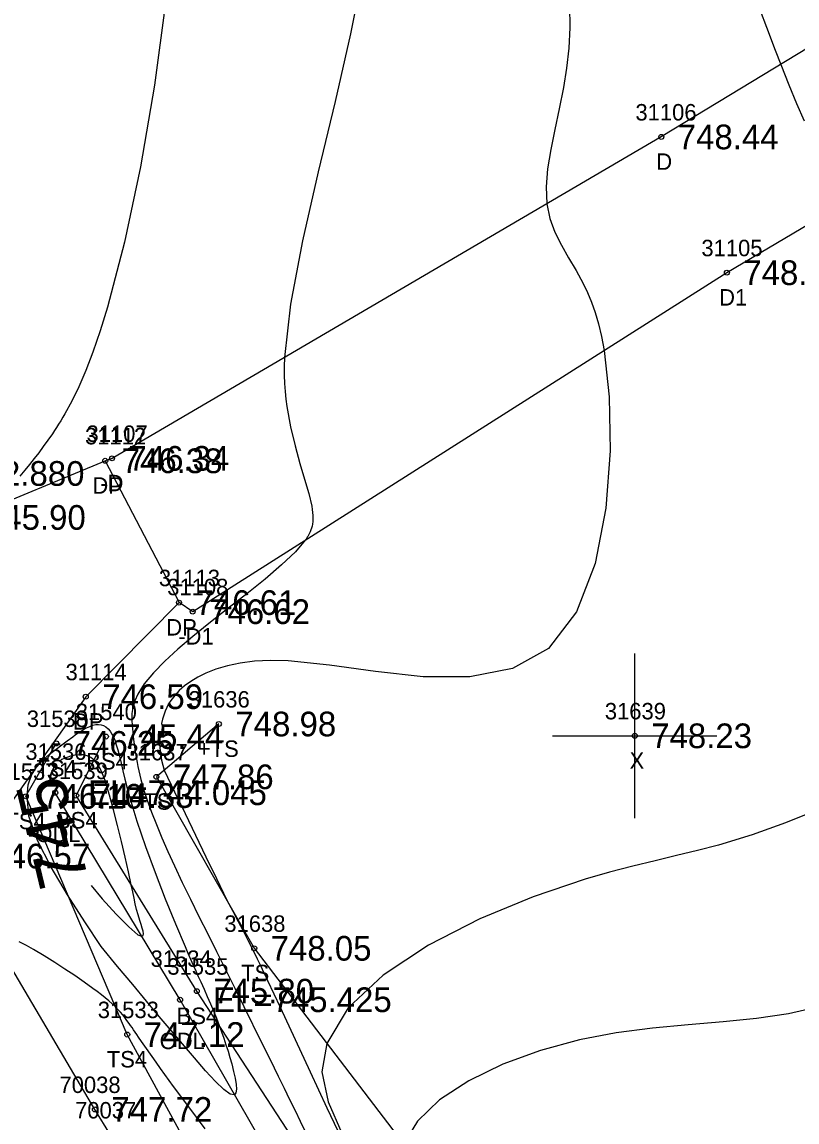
# Model space of a CAD drawing. Extents: x 1376587 to 1378239, y 1000335 to 1003031.
# Drawn here: x 1377894.3 to 1377941.4, y 1000801.1 to 1000868 of the extents above; entities that cross this region are included whole.
import ezdxf

# ---------------------------------------------------------------- set-up
doc = ezdxf.new("R2010")
doc.units = 0
for name, color, linetype in [('RD_DTM_BkLn2', 7, 'Continuous'), ('RD_DTM_BkLn_txCode', 7, 'Continuous'), ('RD_DTM_Major1', 7, 'Continuous'), ('RD_DTM_Major1_Lbl', 7, 'Continuous'), ('RD_DTM_Minor1', 7, 'Continuous'), ('RD_EX_Driveway', 7, 'Continuous'), ('RD_EX_Driveway_txCode', 7, 'Continuous'), ('RD_EX_H2O', 7, 'Continuous'), ('RD_EX_H2O_txCode', 7, 'Continuous'), ('RD_EX_Misc', 7, 'Continuous'), ('RD_EX_Misc_txCode', 7, 'Continuous'), ('RD_EX_Road', 7, 'Continuous'), ('RD_EX_Road_txCode', 7, 'Continuous'), ('RD_EX_TX_Driveway_ELEV', 7, 'Continuous'), ('RD_EX_TX_H2O_ELEV', 7, 'Continuous'), ('RD_EX_TX_Misc_ELEV', 7, 'Continuous'), ('RD_EX_TX_Road_ELEV', 7, 'Continuous'), ('RD_HC_Survey_ELEV', 7, 'Continuous'), ('RD_SMD_Locator', 7, 'Continuous')]:
    doc.layers.add(name, color=color, linetype=linetype)

msp = doc.modelspace()

# ---------------------------------------------------------------- linework, layer by layer
at = {"layer": 'RD_DTM_BkLn2'}
for points in [[(1377906.26, 1000825.275), (1377902.456, 1000822.063), (1377908.408, 1000811.64), (1377936.588, 1000774.744), (1377960.665, 1000733.287), (1377984.073, 1000697.247), (1378009.482, 1000659.726)], [(1378037.054, 1000660.69), (1378019.371, 1000647.154), (1378012.958, 1000645.379), (1378008.902, 1000647.858), (1378005.689, 1000648.466), (1377979.425, 1000689.869), (1377951.959, 1000733.065), (1377926.815, 1000775.481), (1377904.915, 1000809.034), (1377897.581, 1000820.924), (1377899.385, 1000824.511)], [(1378008.67, 1000646.807), (1378003.766, 1000643.675), (1378001.404, 1000645.1), (1377976.657, 1000689.064), (1377948.341, 1000730.353), (1377932.085, 1000752.211), (1377921.755, 1000767.644), (1377900.683, 1000806.395), (1377894.514, 1000820.878), (1377896.367, 1000824.095)]]:
    msp.add_lwpolyline(points, dxfattribs=at)
at = {"layer": 'RD_DTM_Major1'}
for points in [[(1377901.558, 1000812.387), (1377901.642, 1000812.416), (1377901.668, 1000812.517), (1377901.647, 1000812.675), (1377901.595, 1000812.873), (1377901.524, 1000813.095), (1377901.448, 1000813.324), (1377901.343, 1000813.667), (1377901.254, 1000814.002), (1377901.173, 1000814.341), (1377901.097, 1000814.695), (1377901.018, 1000815.075), (1377900.931, 1000815.493), (1377900.76, 1000816.287), (1377900.56, 1000817.18), (1377900.338, 1000818.131), (1377900.1, 1000819.103), (1377899.855, 1000820.057), (1377899.609, 1000820.954), (1377899.471, 1000821.42), (1377899.332, 1000821.85), (1377899.186, 1000822.237), (1377899.03, 1000822.576), (1377898.858, 1000822.86), (1377898.668, 1000823.085), (1377898.461, 1000823.241), (1377898.237, 1000823.342), (1377897.998, 1000823.393), (1377897.749, 1000823.401), (1377897.495, 1000823.372), (1377897.238, 1000823.314), (1377897.059, 1000823.259), (1377896.883, 1000823.192), (1377896.71, 1000823.114), (1377896.652, 1000823.084)], [(1377898.483, 1000815.461), (1377899.162, 1000814.653), (1377900.012, 1000813.716), (1377900.772, 1000812.944), (1377901.326, 1000812.46), (1377901.558, 1000812.387)], [(1377942.592, 1000808.041), (1377940.914, 1000807.665), (1377938.966, 1000807.372), (1377936.928, 1000807.163), (1377934.815, 1000806.984), (1377932.644, 1000806.778), (1377930.433, 1000806.493), (1377928.196, 1000806.074), (1377925.818, 1000805.432), (1377923.536, 1000804.596), (1377921.457, 1000803.588), (1377919.687, 1000802.429), (1377918.331, 1000801.139), (1377917.496, 1000799.741)]]:
    msp.add_lwpolyline(points, dxfattribs=at)
at = {"layer": 'RD_DTM_Minor1'}
for points in [[(1377938.034, 1000871.711), (1377939.576, 1000867.628), (1377940.108, 1000866.23), (1377940.439, 1000865.371), (1377940.925, 1000864.139), (1377941.394, 1000862.994), (1377941.855, 1000861.933)], [(1377914.985, 1000870.919), (1377914.267, 1000867.232), (1377913.323, 1000863.121), (1377912.3, 1000858.841), (1377911.348, 1000854.65), (1377910.613, 1000850.803), (1377910.246, 1000847.558), (1377910.229, 1000846.999), (1377910.231, 1000846.472), (1377910.25, 1000845.97), (1377910.284, 1000845.492), (1377910.332, 1000845.032), (1377910.39, 1000844.586), (1377910.614, 1000843.336), (1377910.889, 1000842.179), (1377911.186, 1000841.117), (1377911.474, 1000840.151), (1377911.723, 1000839.283), (1377911.903, 1000838.516), (1377911.936, 1000838.318), (1377911.961, 1000838.128), (1377911.976, 1000837.944), (1377911.979, 1000837.764), (1377911.969, 1000837.588), (1377911.946, 1000837.414), (1377911.923, 1000837.3), (1377911.892, 1000837.186), (1377911.854, 1000837.071), (1377911.808, 1000836.955), (1377911.753, 1000836.838), (1377911.69, 1000836.719), (1377911.664, 1000836.675), (1377911.637, 1000836.63), (1377911.58, 1000836.54), (1377911.549, 1000836.494), (1377911.516, 1000836.448), (1377910.911, 1000835.737), (1377910.077, 1000834.943), (1377909.074, 1000834.088), (1377907.961, 1000833.196), (1377906.8, 1000832.287), (1377905.65, 1000831.383), (1377904.672, 1000830.592), (1377903.77, 1000829.827), (1377902.965, 1000829.091), (1377902.275, 1000828.388), (1377901.72, 1000827.722), (1377901.318, 1000827.095), (1377901.136, 1000826.682), (1377901.024, 1000826.286), (1377900.97, 1000825.904), (1377900.959, 1000825.531), (1377900.978, 1000825.163), (1377901.013, 1000824.796), (1377901.046, 1000824.5), (1377901.082, 1000824.2), (1377901.122, 1000823.895), (1377901.167, 1000823.583), (1377901.22, 1000823.263), (1377901.281, 1000822.932), (1377901.331, 1000822.683), (1377901.386, 1000822.428), (1377901.448, 1000822.165), (1377901.517, 1000821.894), (1377901.594, 1000821.613), (1377901.679, 1000821.323), (1377901.897, 1000820.646), (1377902.157, 1000819.923), (1377902.455, 1000819.157), (1377902.788, 1000818.354), (1377903.154, 1000817.516), (1377903.549, 1000816.649), (1377904.022, 1000815.649), (1377904.522, 1000814.623), (1377905.042, 1000813.575), (1377905.577, 1000812.511), (1377906.119, 1000811.435), (1377906.663, 1000810.353), (1377907.226, 1000809.225), (1377907.781, 1000808.104), (1377908.856, 1000805.918), (1377909.37, 1000804.87), (1377909.865, 1000803.863), (1377910.22, 1000803.145), (1377910.562, 1000802.451), (1377910.892, 1000801.78), (1377911.209, 1000801.128), (1377911.514, 1000800.493)], [(1377903.006, 1000869.116), (1377902.347, 1000864.103), (1377901.491, 1000859.151), (1377900.512, 1000854.559), (1377899.485, 1000850.622), (1377899.037, 1000849.17), (1377898.594, 1000847.886), (1377898.159, 1000846.756), (1377897.73, 1000845.765), (1377897.309, 1000844.898), (1377896.896, 1000844.139), (1377896.767, 1000843.918), (1377896.638, 1000843.706), (1377896.511, 1000843.501), (1377896.383, 1000843.303), (1377896.257, 1000843.11), (1377896.13, 1000842.922), (1377895.853, 1000842.523), (1377895.577, 1000842.139), (1377895.299, 1000841.769), (1377895.019, 1000841.409), (1377894.736, 1000841.058), (1377894.45, 1000840.713), (1377894.141, 1000840.349)], [(1377927.591, 1000868.916), (1377927.602, 1000867.617), (1377927.538, 1000866.366), (1377927.408, 1000865.151), (1377927.221, 1000863.961), (1377926.968, 1000862.676), (1377926.697, 1000861.418), (1377926.447, 1000860.199), (1377926.257, 1000859.031), (1377926.166, 1000857.925), (1377926.212, 1000856.894), (1377926.4, 1000856.01), (1377926.705, 1000855.181), (1377927.094, 1000854.39), (1377927.533, 1000853.616), (1377927.988, 1000852.843), (1377928.426, 1000852.051), (1377928.692, 1000851.505), (1377928.936, 1000850.927), (1377929.158, 1000850.301), (1377929.357, 1000849.611), (1377929.535, 1000848.841), (1377929.692, 1000847.975), (1377929.991, 1000845.171), (1377930.055, 1000841.874), (1377929.8, 1000838.39), (1377929.145, 1000835.025), (1377928.008, 1000832.084), (1377926.305, 1000829.872), (1377924.123, 1000828.643), (1377921.526, 1000828.14), (1377918.689, 1000828.149), (1377915.785, 1000828.457), (1377912.987, 1000828.849), (1377910.469, 1000829.113), (1377909.401, 1000829.137), (1377908.434, 1000829.09), (1377907.561, 1000828.98), (1377906.778, 1000828.817), (1377906.078, 1000828.608), (1377905.458, 1000828.363), (1377904.976, 1000828.125), (1377904.548, 1000827.868), (1377904.172, 1000827.595), (1377903.847, 1000827.309), (1377903.569, 1000827.013), (1377903.338, 1000826.71), (1377903.202, 1000826.494), (1377903.086, 1000826.275), (1377902.987, 1000826.049), (1377902.903, 1000825.814), (1377902.831, 1000825.569), (1377902.77, 1000825.311), (1377902.897, 1000824.901), (1377902.694, 1000824.533), (1377902.653, 1000824.102), (1377902.688, 1000823.613), (1377902.777, 1000823.068), (1377902.929, 1000822.462), (1377903.564, 1000821.144), (1377904.2, 1000819.827), (1377904.836, 1000818.509), (1377905.471, 1000817.192), (1377906.107, 1000815.874), (1377906.743, 1000814.556), (1377907.106, 1000813.887), (1377907.433, 1000813.274), (1377907.736, 1000812.698), (1377908.023, 1000812.14), (1377908.304, 1000811.58), (1377908.589, 1000811.001), (1377908.689, 1000810.796), (1377908.79, 1000810.586), (1377908.894, 1000810.37), (1377909, 1000810.148), (1377909.108, 1000809.92), (1377909.219, 1000809.686), (1377909.982, 1000808.058), (1377911.807, 1000804.135), (1377912.835, 1000801.941), (1377913.917, 1000799.661)], [(1377894.597, 1000820.888), (1377894.656, 1000821.577), (1377894.859, 1000822.163), (1377895.169, 1000822.659), (1377895.547, 1000823.08), (1377895.957, 1000823.439), (1377896.359, 1000823.75), (1377896.703, 1000824.009), (1377897.037, 1000824.259), (1377897.363, 1000824.498), (1377897.517, 1000824.607), (1377897.665, 1000824.709), (1377897.809, 1000824.804), (1377898.015, 1000824.931), (1377898.213, 1000825.042), (1377898.404, 1000825.131), (1377898.588, 1000825.198), (1377898.764, 1000825.238), (1377898.933, 1000825.25), (1377899.091, 1000825.231), (1377899.242, 1000825.181), (1377899.384, 1000825.1), (1377899.517, 1000824.987), (1377899.64, 1000824.842), (1377899.753, 1000824.665), (1377899.818, 1000824.537), (1377899.88, 1000824.396), (1377899.939, 1000824.242), (1377899.995, 1000824.075), (1377900.05, 1000823.894), (1377900.105, 1000823.7), (1377900.203, 1000823.319), (1377900.305, 1000822.894), (1377900.415, 1000822.428), (1377900.538, 1000821.921), (1377900.677, 1000821.375), (1377900.837, 1000820.789), (1377901.272, 1000819.372), (1377901.797, 1000817.835), (1377902.382, 1000816.24), (1377902.998, 1000814.651), (1377903.614, 1000813.131), (1377904.2, 1000811.744), (1377904.371, 1000811.348), (1377904.698, 1000810.608), (1377904.854, 1000810.26), (1377905.005, 1000809.926), (1377905.15, 1000809.603), (1377905.357, 1000809.146), (1377905.554, 1000808.704), (1377905.745, 1000808.269), (1377905.929, 1000807.835), (1377906.108, 1000807.393), (1377906.283, 1000806.938), (1377906.422, 1000806.558), (1377906.558, 1000806.169), (1377906.689, 1000805.775), (1377906.813, 1000805.382), (1377906.929, 1000804.994), (1377907.036, 1000804.615), (1377907.154, 1000804.157), (1377907.246, 1000803.736), (1377907.306, 1000803.369), (1377907.325, 1000803.07), (1377907.296, 1000802.855), (1377907.211, 1000802.738), (1377906.954, 1000802.776), (1377906.561, 1000803.059), (1377906.051, 1000803.547), (1377905.448, 1000804.198), (1377904.772, 1000804.972), (1377904.044, 1000805.826), (1377903.357, 1000806.639), (1377902.633, 1000807.499), (1377901.857, 1000808.425), (1377901.017, 1000809.431), (1377900.098, 1000810.534), (1377899.087, 1000811.75), (1377898.106, 1000813.248), (1377897.052, 1000814.889), (1377896.049, 1000816.573), (1377895.223, 1000818.201), (1377894.697, 1000819.672), (1377894.597, 1000820.888)], [(1377942.693, 1000820.066), (1377940.736, 1000819.269), (1377938.709, 1000818.546), (1377936.643, 1000817.917), (1377935.382, 1000817.584), (1377934.103, 1000817.273), (1377932.793, 1000816.962), (1377931.439, 1000816.633), (1377930.027, 1000816.265), (1377928.544, 1000815.839), (1377925.384, 1000814.77), (1377922.125, 1000813.423), (1377919.003, 1000811.828), (1377916.255, 1000810.014), (1377914.117, 1000808.013), (1377912.826, 1000805.855), (1377912.524, 1000804.129), (1377912.909, 1000802.308), (1377913.744, 1000800.406)], [(1377905.432, 1000800.664), (1377904.423, 1000801.996), (1377903.506, 1000803.232), (1377902.708, 1000804.332), (1377902.44, 1000804.707), (1377902.191, 1000805.058), (1377901.75, 1000805.689), (1377901.554, 1000805.973), (1377901.373, 1000806.237), (1377901.267, 1000806.391), (1377901.07, 1000806.681), (1377900.976, 1000806.817), (1377900.885, 1000806.949), (1377900.796, 1000807.076), (1377900.667, 1000807.256), (1377900.538, 1000807.43), (1377900.406, 1000807.599), (1377900.267, 1000807.764), (1377900.12, 1000807.928), (1377899.961, 1000808.091), (1377899.772, 1000808.269), (1377899.566, 1000808.449), (1377899.345, 1000808.632), (1377899.109, 1000808.818), (1377898.858, 1000809.008), (1377898.595, 1000809.202), (1377898.063, 1000809.583), (1377897.494, 1000809.976), (1377896.894, 1000810.377), (1377896.27, 1000810.778), (1377895.63, 1000811.174), (1377894.979, 1000811.559), (1377894.545, 1000811.805), (1377894.106, 1000812.041)]]:
    msp.add_lwpolyline(points, dxfattribs=at)
at = {"layer": 'RD_EX_Driveway'}
for points in [[(1377966.861, 1000881.398), (1377933.173, 1000860.964), (1377899.756, 1000841.424), (1377899.343, 1000841.276)], [(1377971.901, 1000873.272), (1377937.162, 1000852.712), (1377904.665, 1000832.103), (1377903.835, 1000832.654)], [(1377878.336, 1000836.547), (1377891.027, 1000837.833), (1377899.343, 1000841.276), (1377903.835, 1000832.654), (1377898.158, 1000826.934), (1377891.293, 1000817.241)]]:
    msp.add_lwpolyline(points, dxfattribs=at)
at = {"layer": 'RD_EX_H2O'}
msp.add_lwpolyline([(1378004.897, 1000647.311), (1377978.29, 1000689.615), (1377950.659, 1000732.22), (1377923.852, 1000773.755), (1377903.897, 1000808.511), (1377896.301, 1000821.096)], dxfattribs=at)
at = {"layer": 'RD_EX_Misc'}
for p, q in [((1377931.556, 1000819.556), (1377931.556, 1000829.556)), ((1377926.556, 1000824.556), (1377936.556, 1000824.556))]:
    msp.add_line(p, q, dxfattribs=at)
at = {"layer": 'RD_EX_Road'}
msp.add_lwpolyline([(1377899.668, 1000800.294), (1377898.717, 1000801.843), (1377870.308, 1000849.935), (1377847.281, 1000887.888), (1377815.153, 1000940.575), (1377781.512, 1000995.259), (1377748.623, 1001049.208), (1377716.579, 1001099.532), (1377686.671, 1001148.78), (1377656.469, 1001199.107), (1377629.542, 1001244.184), (1377599.886, 1001292.672), (1377570.873, 1001341.428), (1377539.828, 1001392.468), (1377511.01, 1001440.306), (1377480.717, 1001489.998), (1377449.725, 1001541.494), (1377420.899, 1001591.946), (1377390.45, 1001644.414)], dxfattribs=at)
at = {"layer": 'RD_SMD_Locator'}
for centre in [(1377933.173, 1000860.964), (1377937.162, 1000852.712), (1377899.756, 1000841.424), (1377899.343, 1000841.276), (1377903.835, 1000832.654), (1377904.665, 1000832.103), (1377898.158, 1000826.934), (1377906.26, 1000825.275), (1377896.367, 1000824.095), (1377899.385, 1000824.511), (1377931.556, 1000824.556), (1377902.456, 1000822.063), (1377894.514, 1000820.878), (1377896.301, 1000821.096), (1377897.581, 1000820.924), (1377908.408, 1000811.64), (1377904.915, 1000809.034), (1377903.897, 1000808.511), (1377900.683, 1000806.395), (1377898.717, 1000801.843)]:
    msp.add_circle(centre, 0.15, dxfattribs=at)

# ---------------------------------------------------------------- texts
at = {"layer": 'RD_DTM_BkLn_txCode'}
for s, p in [('31636', (1377904.417, 1000826.275)), ('31540', (1377897.55, 1000825.511)), ('31538', (1377894.572, 1000825.095)), ('+TS', (1377904.977, 1000823.275)), ('-BS4', (1377897.747, 1000822.511)), ('31637', (1377900.637, 1000823.063)), ('31537', (1377892.719, 1000821.878)), ('-TS4', (1377894.713, 1000822.095)), ('31539', (1377895.786, 1000821.924)), ('TS', (1377901.661, 1000820.063)), ('TS4', (1377893.27, 1000818.878)), ('BS4', (1377896.353, 1000818.924)), ('31638', (1377906.589, 1000812.64)), ('31535', (1377903.12, 1000810.034)), ('TS', (1377907.613, 1000809.64)), ('31533', (1377898.888, 1000807.395)), ('BS4', (1377903.687, 1000807.034)), ('TS4', (1377899.439, 1000804.395))]:
    msp.add_text(s, height=1, dxfattribs=at).set_placement(p)
at = {"layer": 'RD_DTM_Major1_Lbl'}
msp.add_text('745', height=3, rotation=103.50856, dxfattribs=at).set_placement((1377898.348, 1000815.75))
at = {"layer": 'RD_EX_Driveway_txCode'}
for s, p in [('31106', (1377931.598, 1000861.964)), ('D', (1377932.866, 1000858.964)), ('31105', (1377935.611, 1000853.712)), ('D1', (1377936.69, 1000850.712)), ('31112', (1377898.115, 1000842.276)), ('31107', (1377898.205, 1000842.424)), ('DP', (1377898.563, 1000839.276)), ('-D', (1377899.039, 1000839.424)), ('31113', (1377902.607, 1000833.654)), ('31108', (1377903.114, 1000833.103)), ('DP', (1377903.055, 1000830.654)), ('-D1', (1377903.783, 1000830.103)), ('31114', (1377896.93, 1000827.934)), ('DP', (1377897.378, 1000824.934))]:
    msp.add_text(s, height=1, dxfattribs=at).set_placement(p)
at = {"layer": 'RD_EX_H2O_txCode'}
for s, p in [('31536', (1377894.482, 1000823.096)), ('-ODL', (1377894.647, 1000818.096)), ('31534', (1377902.102, 1000810.511)), ('ODL', (1377902.653, 1000805.511))]:
    msp.add_text(s, height=1, dxfattribs=at).set_placement(p)
at = {"layer": 'RD_EX_Misc_txCode'}
for s, p in [('31639', (1377929.737, 1000825.556)), ('X', (1377931.241, 1000822.556))]:
    msp.add_text(s, height=1, dxfattribs=at).set_placement(p)
at = {"layer": 'RD_EX_Road_txCode'}
for s, p in [('70038', (1377896.56, 1000802.843)), ('70037', (1377897.511, 1000801.294))]:
    msp.add_text(s, height=1, dxfattribs=at).set_placement(p)
at = {"layer": 'RD_EX_TX_Driveway_ELEV'}
for s, p in [('748.44', (1377934.173, 1000860.214)), ('748.41', (1377938.162, 1000851.962)), ('746.38', (1377900.343, 1000840.526)), ('746.34', (1377900.756, 1000840.674)), ('745.90', (1377892.027, 1000837.083)), ('746.61', (1377904.835, 1000831.904)), ('746.62', (1377905.665, 1000831.353)), ('746.59', (1377899.158, 1000826.184)), ('746.57', (1377892.293, 1000816.491))]:
    msp.add_text(s, height=1.5, dxfattribs=at).set_placement(p)
at = {"layer": 'RD_EX_TX_H2O_ELEV'}
for s, p in [('EL=742.880', (1377887.206, 1000839.756)), ('EL=744.045', (1377898.301, 1000820.346)), ('EL=745.425', (1377905.897, 1000807.761))]:
    msp.add_text(s, height=1.5, dxfattribs=at).set_placement(p)
at = {"layer": 'RD_EX_TX_Misc_ELEV'}
for s, p in [('748.98', (1377907.26, 1000824.525)), ('746.25', (1377897.367, 1000823.345)), ('745.44', (1377900.385, 1000823.761)), ('748.23', (1377932.556, 1000823.806)), ('747.86', (1377903.456, 1000821.313)), ('746.10', (1377895.514, 1000820.128)), ('744.33', (1377898.581, 1000820.174)), ('748.05', (1377909.408, 1000810.89)), ('745.80', (1377905.915, 1000808.284)), ('747.12', (1377901.683, 1000805.645))]:
    msp.add_text(s, height=1.5, dxfattribs=at).set_placement(p)
at = {"layer": 'RD_EX_TX_Road_ELEV'}
msp.add_text('747.72', height=1.5, dxfattribs=at).set_placement((1377899.717, 1000801.093))
at = {"layer": 'RD_HC_Survey_ELEV'}
msp.add_text('747.72', height=1.5, dxfattribs=at).set_placement((1377899.717, 1000801.093))

doc.saveas('drawing.dxf')
